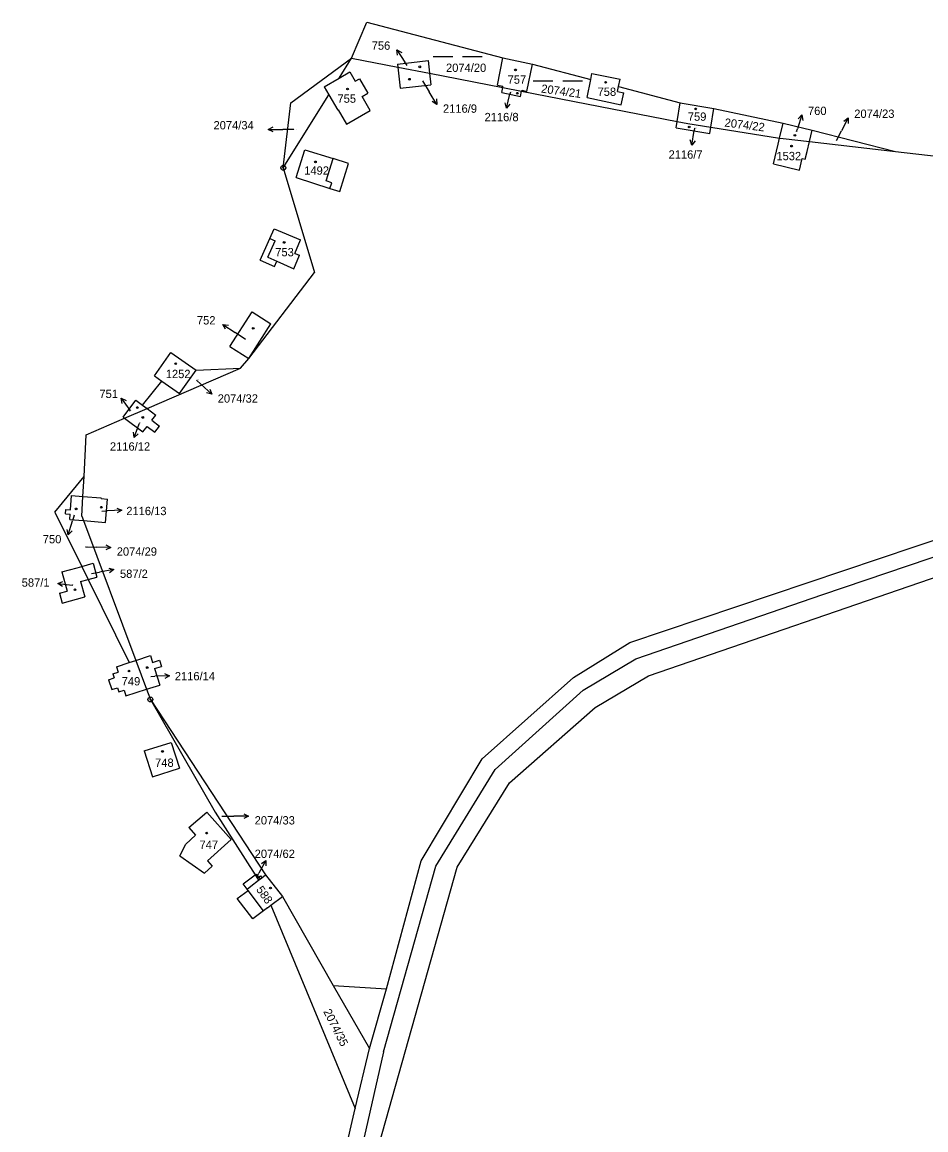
# Model space of a CAD drawing. Extents: x -763205 to -760228, y -1155311 to -1152844.
# Drawn here: x -762430.5 to -762245.9, y -1154041.9 to -1153815.6 of the extents above; entities that cross this region are included whole.
import ezdxf

# ---------------------------------------------------------------- set-up
doc = ezdxf.new("R2010")
doc.units = 0
for name, color, linetype in [('Vrstva 1', 7, 'Continuous'), ('Vrstva 10', 7, 'Continuous'), ('Vrstva 16', 7, 'Continuous'), ('Vrstva 18', 7, 'Continuous'), ('Vrstva 19', 7, 'Continuous'), ('Vrstva 24', 7, 'Continuous'), ('Vrstva 25', 7, 'Continuous'), ('Vrstva 4', 7, 'Continuous'), ('Vrstva 6', 7, 'Continuous')]:
    doc.layers.add(name, color=color, linetype=linetype)

msp = doc.modelspace()

# ---------------------------------------------------------------- linework, layer by layer
at = {"layer": 'Vrstva 1'}
for p, q in [((-762365.73, -1153827.07), (-762363.18, -1153822.97)), ((-762363.18, -1153822.97), (-762353.7, -1153824.82)), ((-762353.76, -1153824.23), (-762347.55, -1153823.47)), ((-762353.76, -1153824.23), (-762353.7, -1153824.82)), ((-762347.55, -1153823.47), (-762347.23, -1153826.07)), ((-762333.38, -1153828.49), (-762332.24, -1153822.94)), ((-762332.24, -1153822.94), (-762326.22, -1153824.18)), ((-762327.37, -1153829.76), (-762326.22, -1153824.18)), ((-762368.76, -1153828.84), (-762365.73, -1153827.07)), ((-762365.73, -1153827.07), (-762363.51, -1153825.78)), ((-762363.51, -1153825.78), (-762362.4, -1153827.69)), ((-762353.7, -1153824.82), (-762353.23, -1153829.12)), ((-762353.7, -1153824.82), (-762347.23, -1153826.07)), ((-762347.23, -1153826.07), (-762346.95, -1153828.41)), ((-762347.23, -1153826.07), (-762332.29, -1153828.98)), ((-762314.29, -1153827.31), (-762314.06, -1153826.1)), ((-762314.06, -1153826.1), (-762308.31, -1153827.26)), ((-762368.76, -1153828.84), (-762367.83, -1153830.44)), ((-762362.4, -1153827.69), (-762361.57, -1153827.21)), ((-762361.57, -1153827.21), (-762359.87, -1153830.12)), ((-762353.23, -1153829.12), (-762346.95, -1153828.41)), ((-762333.38, -1153828.49), (-762332.24, -1153828.73)), ((-762332.5, -1153829.96), (-762332.29, -1153828.98)), ((-762332.29, -1153828.98), (-762332.24, -1153828.73)), ((-762332.29, -1153828.98), (-762328.45, -1153829.73)), ((-762315.01, -1153831.04), (-762314.29, -1153827.31)), ((-762308.84, -1153829.79), (-762308.63, -1153828.8)), ((-762308.63, -1153828.8), (-762308.31, -1153827.26)), ((-762377.11, -1153845.38), (-762367.83, -1153830.44)), ((-762367.83, -1153830.44), (-762365.98, -1153833.61)), ((-762361.02, -1153830.78), (-762359.87, -1153830.12)), ((-762359.37, -1153833.66), (-762361.02, -1153830.78)), ((-762332.5, -1153829.96), (-762328.68, -1153830.79)), ((-762328.68, -1153830.79), (-762328.45, -1153829.73)), ((-762328.45, -1153829.73), (-762328.41, -1153829.54)), ((-762328.45, -1153829.73), (-762296.66, -1153835.92)), ((-762328.41, -1153829.54), (-762327.37, -1153829.76)), ((-762315.01, -1153831.04), (-762308.06, -1153832.5)), ((-762308.84, -1153829.79), (-762307.55, -1153830.06)), ((-762308.06, -1153832.5), (-762307.55, -1153830.06)), ((-762365.98, -1153833.61), (-762365.89, -1153833.56)), ((-762365.89, -1153833.56), (-762364.23, -1153836.46)), ((-762364.23, -1153836.46), (-762359.37, -1153833.66)), ((-762296.66, -1153835.92), (-762296.02, -1153832.12)), ((-762296.02, -1153832.12), (-762289.13, -1153833.27)), ((-762289.77, -1153837.08), (-762289.13, -1153833.27)), ((-762296.87, -1153837.2), (-762296.66, -1153835.92)), ((-762296.66, -1153835.92), (-762294.44, -1153836.35)), ((-762296.87, -1153837.2), (-762289.99, -1153838.4)), ((-762294.44, -1153836.35), (-762289.77, -1153837.08)), ((-762289.99, -1153838.4), (-762289.77, -1153837.08)), ((-762289.77, -1153837.08), (-762275.73, -1153839.29)), ((-762275.73, -1153839.29), (-762275.01, -1153836.29)), ((-762275.01, -1153836.29), (-762269.07, -1153837.69)), ((-762269.63, -1153840.02), (-762269.07, -1153837.69)), ((-762277, -1153844.56), (-762276.04, -1153840.57)), ((-762276.04, -1153840.57), (-762275.73, -1153839.29)), ((-762275.73, -1153839.29), (-762275, -1153839.4)), ((-762275, -1153839.4), (-762269.63, -1153840.02)), ((-762270.12, -1153842.08), (-762269.63, -1153840.02)), ((-762269.63, -1153840.02), (-762252.02, -1153842.05)), ((-762374.49, -1153847.39), (-762372.68, -1153841.68)), ((-762372.68, -1153841.68), (-762366.9, -1153843.51)), ((-762270.49, -1153843.63), (-762270.12, -1153842.08)), ((-762252.02, -1153842.05), (-762239.69, -1153843.48)), ((-762363.78, -1153844.5), (-762366.9, -1153843.51)), ((-762365.58, -1153850.24), (-762363.78, -1153844.5)), ((-762277, -1153844.56), (-762271.68, -1153845.85)), ((-762271.68, -1153845.85), (-762271.11, -1153843.48)), ((-762271.11, -1153843.48), (-762270.49, -1153843.63)), ((-762377.11, -1153845.38), (-762370.77, -1153866.79)), ((-762374.49, -1153847.39), (-762367.58, -1153849.6)), ((-762367.58, -1153849.6), (-762365.58, -1153850.24)), ((-762379.89, -1153859.84), (-762378.99, -1153857.82)), ((-762378.99, -1153857.82), (-762373.58, -1153860.13)), ((-762381.85, -1153864.23), (-762379.89, -1153859.84)), ((-762374.75, -1153862.86), (-762373.58, -1153860.13)), ((-762374.99, -1153866), (-762373.82, -1153863.26)), ((-762374.75, -1153862.86), (-762373.82, -1153863.26)), ((-762381.85, -1153864.23), (-762378.92, -1153865.57)), ((-762378.92, -1153865.57), (-762378.4, -1153864.44)), ((-762378.4, -1153864.44), (-762374.99, -1153866)), ((-762384.13, -1153884.34), (-762370.77, -1153866.79)), ((-762388.02, -1153881.92), (-762383.47, -1153874.82)), ((-762383.47, -1153874.82), (-762379.65, -1153877.23)), ((-762384.13, -1153884.34), (-762379.65, -1153877.23)), ((-762403.45, -1153887.86), (-762400.08, -1153883.1)), ((-762400.08, -1153883.1), (-762394.94, -1153886.74)), ((-762388.02, -1153881.92), (-762384.13, -1153884.34)), ((-762385.85, -1153886.35), (-762384.13, -1153884.34)), ((-762404.95, -1153894.58), (-762385.85, -1153886.35)), ((-762403.45, -1153887.86), (-762401.9, -1153888.96)), ((-762398.31, -1153891.5), (-762394.94, -1153886.74)), ((-762401.9, -1153888.96), (-762398.31, -1153891.5)), ((-762409.79, -1153896.35), (-762407.22, -1153892.87)), ((-762409.52, -1153896.55), (-762404.95, -1153894.58)), ((-762407.22, -1153892.87), (-762405.88, -1153893.88)), ((-762405.88, -1153893.88), (-762404.95, -1153894.58)), ((-762404.95, -1153894.58), (-762403.18, -1153895.91)), ((-762417.36, -1153899.93), (-762409.52, -1153896.55)), ((-762409.79, -1153896.35), (-762409.52, -1153896.55)), ((-762409.52, -1153896.55), (-762405.8, -1153899.36)), ((-762403.99, -1153896.97), (-762403.18, -1153895.91)), ((-762403.99, -1153896.97), (-762402.43, -1153898.15)), ((-762405.8, -1153899.36), (-762404.93, -1153898.21)), ((-762404.93, -1153898.21), (-762403.37, -1153899.39)), ((-762403.37, -1153899.39), (-762402.43, -1153898.15)), ((-762417.81, -1153908.43), (-762417.36, -1153899.93)), ((-762418.03, -1153912.51), (-762417.81, -1153908.43)), ((-762306.29, -1153942.34), (-762207.83, -1153909.23)), ((-762420.58, -1153915.27), (-762420.36, -1153912.33)), ((-762420.36, -1153912.33), (-762418.03, -1153912.51)), ((-762418.24, -1153916.56), (-762418.03, -1153912.51)), ((-762418.03, -1153912.51), (-762414.29, -1153912.81)), ((-762414.31, -1153912.96), (-762414.29, -1153912.81)), ((-762414.31, -1153912.96), (-762413.01, -1153913.06)), ((-762413.41, -1153917.83), (-762413.01, -1153913.06)), ((-762421.62, -1153916.1), (-762421.55, -1153915.2)), ((-762421.55, -1153915.2), (-762420.58, -1153915.27)), ((-762421.62, -1153916.1), (-762420.64, -1153916.17)), ((-762420.72, -1153917.22), (-762420.64, -1153916.17)), ((-762420.72, -1153917.22), (-762417.91, -1153917.45)), ((-762418.24, -1153916.56), (-762417.91, -1153917.45)), ((-762417.91, -1153917.45), (-762413.41, -1153917.83)), ((-762417.91, -1153917.45), (-762407.24, -1153946.03)), ((-762302.52, -1153949.17), (-762204.97, -1153915.64)), ((-762418.28, -1153926.85), (-762415.96, -1153926.18)), ((-762415.96, -1153926.18), (-762415.19, -1153929.03)), ((-762422.32, -1153927.9), (-762419.2, -1153927.12)), ((-762422.32, -1153927.9), (-762421.23, -1153931.86)), ((-762419.2, -1153927.12), (-762418.28, -1153926.85)), ((-762418.51, -1153929.94), (-762416.96, -1153929.52)), ((-762418.51, -1153929.94), (-762417.65, -1153933.06)), ((-762416.96, -1153929.52), (-762415.19, -1153929.03)), ((-762422.8, -1153932.29), (-762421.23, -1153931.86)), ((-762422.8, -1153932.29), (-762422.27, -1153934.35)), ((-762422.27, -1153934.35), (-762417.65, -1153933.06)), ((-762317.85, -1153949.52), (-762306.29, -1153942.34)), ((-762411.2, -1153947.32), (-762408.6, -1153946.47)), ((-762408.6, -1153946.47), (-762407.24, -1153946.03)), ((-762407.24, -1153946.03), (-762404.26, -1153945.06)), ((-762407.24, -1153946.03), (-762405.04, -1153951.93)), ((-762404.26, -1153945.06), (-762403.81, -1153946.46)), ((-762403.81, -1153946.46), (-762402.37, -1153945.99)), ((-762402.37, -1153945.99), (-762401.96, -1153947.24)), ((-762411.93, -1153948.76), (-762410.84, -1153948.41)), ((-762411.93, -1153948.76), (-762411.65, -1153949.61)), ((-762411.2, -1153947.32), (-762410.84, -1153948.41)), ((-762403.4, -1153947.71), (-762401.96, -1153947.24)), ((-762403.4, -1153947.71), (-762402.32, -1153951.08)), ((-762313.42, -1153955.63), (-762302.52, -1153949.17)), ((-762412.79, -1153949.98), (-762411.65, -1153949.61)), ((-762412.79, -1153949.98), (-762412.14, -1153951.97)), ((-762405.04, -1153951.93), (-762402.32, -1153951.08)), ((-762336.52, -1153966.17), (-762317.85, -1153949.52)), ((-762412.14, -1153951.97), (-762411.01, -1153951.6)), ((-762411.01, -1153951.6), (-762410.73, -1153952.46)), ((-762410.73, -1153952.46), (-762409.64, -1153952.1)), ((-762409.64, -1153952.1), (-762409.27, -1153953.24)), ((-762409.27, -1153953.24), (-762405.04, -1153951.93)), ((-762405.04, -1153951.93), (-762404.26, -1153954.02)), ((-762404.26, -1153954.02), (-762380.73, -1153989.83)), ((-762330.92, -1153971.05), (-762313.42, -1153955.63)), ((-762405.54, -1153964.53), (-762400.01, -1153962.78)), ((-762400.01, -1153962.78), (-762398.32, -1153968.04)), ((-762405.54, -1153964.53), (-762403.85, -1153969.81)), ((-762348.93, -1153987.01), (-762336.52, -1153966.17)), ((-762403.85, -1153969.81), (-762398.32, -1153968.04)), ((-762341.62, -1153988.29), (-762330.92, -1153971.05)), ((-762396.42, -1153980.19), (-762392.71, -1153977.03)), ((-762392.71, -1153977.03), (-762387.73, -1153982.61)), ((-762396.42, -1153980.19), (-762395.05, -1153981.76)), ((-762397.02, -1153983.55), (-762395.05, -1153981.76)), ((-762392.61, -1153986.99), (-762387.73, -1153982.61)), ((-762398.22, -1153985.97), (-762397.02, -1153983.55)), ((-762398.22, -1153985.97), (-762393.21, -1153989.53)), ((-762392.61, -1153986.99), (-762391.61, -1153988.1)), ((-762356.01, -1154013.13), (-762348.93, -1153987.01)), ((-762393.21, -1153989.53), (-762391.61, -1153988.1)), ((-762385.31, -1153991.71), (-762382.85, -1153989.87)), ((-762382.85, -1153989.87), (-762382.63, -1153989.71)), ((-762382.63, -1153989.71), (-762382.15, -1153990.35)), ((-762381.51, -1153990.44), (-762380.73, -1153989.83)), ((-762380.73, -1153989.83), (-762377.29, -1153994.25)), ((-762363.03, -1154064.25), (-762341.62, -1153988.29)), ((-762384.49, -1153992.78), (-762385.31, -1153991.71)), ((-762382.16, -1153990.95), (-762381.51, -1153990.44)), ((-762382.15, -1153990.35), (-762381.78, -1153990.07)), ((-762381.78, -1153990.07), (-762381.51, -1153990.44)), ((-762386.51, -1153994.66), (-762384.32, -1153993.01)), ((-762384.32, -1153993.01), (-762384.49, -1153992.78)), ((-762379.64, -1153996.04), (-762377.29, -1153994.25)), ((-762377.29, -1153994.25), (-762366.9, -1154012.43)), ((-762383.32, -1153998.84), (-762386.51, -1153994.66)), ((-762380.35, -1153996.58), (-762381.16, -1153997.2)), ((-762380.35, -1153996.58), (-762379.64, -1153996.04)), ((-762381.16, -1153997.2), (-762383.32, -1153998.84)), ((-762366.9, -1154012.43), (-762356.01, -1154013.13)), ((-762359.53, -1154025.33), (-762356.01, -1154013.13)), ((-762362.41, -1154037.61), (-762359.53, -1154025.33)), ((-762366.48, -1154054.98), (-762362.41, -1154037.61))]:
    msp.add_line(p, q, dxfattribs=at)
at = {"layer": 'Vrstva 10'}
for p, q in [((-762266.9, -1153932.54), (-762236.2, -1153922.19)), ((-762305.1, -1153945.73), (-762266.9, -1153932.54)), ((-762315.83, -1153952.13), (-762305.1, -1153945.73)), ((-762333.86, -1153968.33), (-762315.83, -1153952.13)), ((-762345.92, -1153988.07), (-762333.86, -1153968.33)), ((-762356.66, -1154026.02), (-762345.92, -1153988.07)), ((-762356.66, -1154026.02), (-762361.72, -1154048.42))]:
    msp.add_line(p, q, dxfattribs=at)
at = {"layer": 'Vrstva 16'}
for p, q in [((-762353.886, -1153821.263), (-762352.27, -1153823.79)), ((-762351.83, -1153824.48), (-762352.27, -1153823.79)), ((-762348.7, -1153827.59), (-762347.3, -1153829.87)), ((-762345.731, -1153832.427), (-762347.3, -1153829.87)), ((-762331.53, -1153833.227), (-762330.83, -1153830.31)), ((-762330.73, -1153829.9), (-762330.83, -1153830.31)), ((-762271.173, -1153834.587), (-762272.1, -1153837.44)), ((-762261.723, -1153835.18), (-762263.09, -1153837.85)), ((-762380.21, -1153837.531), (-762377.21, -1153837.53)), ((-762374.93, -1153837.53), (-762377.21, -1153837.53)), ((-762293.626, -1153840.755), (-762293.17, -1153837.79)), ((-762293.1, -1153837.31), (-762293.17, -1153837.79)), ((-762272.27, -1153837.97), (-762272.1, -1153837.44)), ((-762264.08, -1153839.79), (-762263.09, -1153837.85)), ((-762389.446, -1153877.386), (-762386.95, -1153879.05)), ((-762384.86, -1153880.45), (-762386.95, -1153879.05)), ((-762394.85, -1153888.77), (-762393.94, -1153889.62)), ((-762391.742, -1153891.661), (-762393.94, -1153889.62)), ((-762410.213, -1153892.421), (-762408.48, -1153894.87)), ((-762408.29, -1153895.13), (-762408.48, -1153894.87)), ((-762407.576, -1153900.483), (-762406.56, -1153897.66)), ((-762406.51, -1153897.51), (-762406.56, -1153897.66)), ((-762421.034, -1153920.396), (-762420.18, -1153917.52)), ((-762419.82, -1153916.32), (-762420.18, -1153917.52)), ((-762414.16, -1153915.55), (-762413.06, -1153915.5)), ((-762410.063, -1153915.36), (-762413.06, -1153915.5)), ((-762417.52, -1153922.82), (-762415.37, -1153922.87)), ((-762412.371, -1153922.934), (-762415.37, -1153922.87)), ((-762416.31, -1153928.29), (-762414.66, -1153928)), ((-762411.707, -1153927.473), (-762414.66, -1153928)), ((-762423.164, -1153930.332), (-762420.18, -1153930.64)), ((-762420.07, -1153930.65), (-762420.18, -1153930.64)), ((-762404.16, -1153949.31), (-762403.35, -1153949.28)), ((-762400.352, -1153949.161), (-762403.35, -1153949.28)), ((-762389.67, -1153977.85), (-762387.2, -1153977.85)), ((-762384.2, -1153977.851), (-762387.2, -1153977.85)), ((-762380.662, -1153986.892), (-762382.09, -1153989.53)), ((-762382.46, -1153990.2), (-762382.09, -1153989.53))]:
    msp.add_line(p, q, dxfattribs=at)
for points in [[(-762353.769, -1153822.375), (-762353.886, -1153821.263), (-762352.926, -1153821.836)], [(-762345.828, -1153831.313), (-762345.731, -1153832.427), (-762346.68, -1153831.836)], [(-762330.811, -1153832.371), (-762331.53, -1153833.227), (-762331.783, -1153832.138)], [(-762271.957, -1153835.383), (-762271.173, -1153834.587), (-762271.006, -1153835.692)], [(-762262.624, -1153835.842), (-762261.723, -1153835.18), (-762261.733, -1153836.298)], [(-762379.21, -1153838.03), (-762380.21, -1153837.531), (-762379.21, -1153837.03)], [(-762292.98, -1153839.843), (-762293.626, -1153840.755), (-762293.968, -1153839.691)], [(-762388.892, -1153878.357), (-762389.446, -1153877.386), (-762388.337, -1153877.525)], [(-762410.044, -1153893.526), (-762410.213, -1153892.421), (-762409.227, -1153892.949)], [(-762392.134, -1153890.615), (-762391.742, -1153891.661), (-762392.815, -1153891.347)], [(-762406.767, -1153899.711), (-762407.576, -1153900.483), (-762407.708, -1153899.372)], [(-762411.085, -1153914.907), (-762410.063, -1153915.36), (-762411.039, -1153915.906)], [(-762420.27, -1153919.58), (-762421.034, -1153920.396), (-762421.229, -1153919.295)], [(-762413.36, -1153922.413), (-762412.371, -1153922.934), (-762413.381, -1153923.413)], [(-762412.779, -1153927.156), (-762411.707, -1153927.473), (-762412.603, -1153928.141)], [(-762422.221, -1153930.932), (-762423.164, -1153930.332), (-762422.118, -1153929.937)], [(-762401.371, -1153948.701), (-762400.352, -1153949.161), (-762401.332, -1153949.7)], [(-762385.2, -1153977.351), (-762384.2, -1153977.851), (-762385.2, -1153978.351)], [(-762381.578, -1153987.533), (-762380.662, -1153986.892), (-762380.698, -1153988.009)]]:
    msp.add_lwpolyline(points, dxfattribs=at)
at = {"layer": 'Vrstva 24'}
for centre, radius in [((-762377.11, -1153845.38), 0.5), ((-762377.11, -1153845.38), 0.1), ((-762404.26, -1153954.02), 0.5), ((-762404.26, -1153954.02), 0.1)]:
    msp.add_circle(centre, radius, dxfattribs=at)
at = {"layer": 'Vrstva 25'}
for p, q in [((-762346.515, -1153822.64), (-762342.495, -1153822.64)), ((-762340.485, -1153822.64), (-762336.465, -1153822.64)), ((-762326.045, -1153827.63), (-762322.025, -1153827.63)), ((-762320.015, -1153827.63), (-762315.995, -1153827.63))]:
    msp.add_line(p, q, dxfattribs=at)
for centre in [(-762349.23, -1153824.75), (-762329.68, -1153825.38), (-762363.98, -1153829.29), (-762351.35, -1153827.28), (-762311.26, -1153827.91), (-762329.31, -1153830.15), (-762292.87, -1153833.35), (-762294.19, -1153837.04), (-762272.61, -1153838.74), (-762273.28, -1153840.95), (-762370.54, -1153844.18), (-762376.93, -1153860.63), (-762383.26, -1153878.18), (-762399.09, -1153885.41), (-762406.93, -1153894.37), (-762405.81, -1153896.39), (-762419.44, -1153915.07), (-762414.29, -1153914.73), (-762419.66, -1153931.6), (-762408.64, -1153948.2), (-762404.9, -1153947.49), (-762401.79, -1153964.62), (-762392.76, -1153981.32), (-762382.11, -1153990.59), (-762379.72, -1153992.54)]:
    msp.add_circle(centre, 0.175, dxfattribs=at)
at = {"layer": 'Vrstva 4'}
for p, q in [((-762368.36, -1153848.06), (-762366.9, -1153843.51)), ((-762367.21, -1153848.43), (-762368.36, -1153848.06)), ((-762367.58, -1153849.6), (-762367.21, -1153848.43)), ((-762380.29, -1153863.67), (-762378.8, -1153860.33)), ((-762379.89, -1153859.84), (-762378.8, -1153860.33)), ((-762380.29, -1153863.67), (-762378.4, -1153864.44)), ((-762384.49, -1153992.78), (-762383.71, -1153992.16)), ((-762383.71, -1153992.16), (-762382.16, -1153990.95)), ((-762381.16, -1153997.2), (-762384.32, -1153993.01)), ((-762366.9, -1154012.43), (-762359.53, -1154025.33))]:
    msp.add_line(p, q, dxfattribs=at)
at = {"layer": 'Vrstva 6'}
for p, q in [((-762363.18, -1153822.97), (-762360.04, -1153815.62)), ((-762360.04, -1153815.62), (-762332.24, -1153822.94)), ((-762375.58, -1153832.13), (-762363.18, -1153822.97)), ((-762326.22, -1153824.18), (-762314.29, -1153827.31)), ((-762308.63, -1153828.8), (-762296.02, -1153832.12)), ((-762377.11, -1153845.38), (-762375.58, -1153832.13)), ((-762289.13, -1153833.27), (-762275.01, -1153836.29)), ((-762269.07, -1153837.69), (-762252.02, -1153842.05)), ((-762394.94, -1153886.74), (-762385.85, -1153886.35)), ((-762405.88, -1153893.88), (-762401.9, -1153888.96)), ((-762423.78, -1153915.71), (-762417.81, -1153908.43)), ((-762423.78, -1153915.71), (-762418.28, -1153926.85)), ((-762418.28, -1153926.85), (-762416.96, -1153929.52)), ((-762416.96, -1153929.52), (-762408.6, -1153946.47)), ((-762404.26, -1153954.02), (-762391.04, -1153977.05)), ((-762391.04, -1153977.05), (-762382.85, -1153989.87)), ((-762382.85, -1153989.87), (-762382.16, -1153990.95)), ((-762379.64, -1153996.04), (-762362.41, -1154037.61))]:
    msp.add_line(p, q, dxfattribs=at)

# ---------------------------------------------------------------- texts
at = {"layer": 'Vrstva 16'}
for s, p in [('756', (-762359.05, -1153821.26)), ('2116/9', (-762344.493, -1153834.13)), ('760', (-762269.933, -1153834.59)), ('2074/23', (-762260.483, -1153835.18)), ('2074/34', (-762391.366, -1153837.53)), ('2116/8', (-762335.998, -1153835.86)), ('2116/7', (-762298.408, -1153843.51)), ('752', (-762394.757, -1153877.39)), ('751', (-762414.674, -1153892.42)), ('2074/32', (-762390.503, -1153893.36)), ('2116/12', (-762412.528, -1153903.17)), ('2116/13', (-762409.183, -1153916.35)), ('750', (-762426.243, -1153922.1)), ('2074/29', (-762411.133, -1153924.63)), ('587/2', (-762410.473, -1153929.17)), ('587/1', (-762430.545, -1153930.97)), ('2116/14', (-762399.273, -1153950.1)), ('2074/33', (-762382.963, -1153979.55)), ('2074/62', (-762382.956, -1153986.39))]:
    msp.add_text(s, height=1.7, dxfattribs=at).set_placement(p)
at = {"layer": 'Vrstva 18'}
for s, height, p in [('2074/20', 1.7, (-762343.873, -1153825.79)), ('2116/9', 0.1, (-762348.686, -1153827.59)), ('2116/8', 0.1, (-762330.716, -1153829.9)), ('2074/34', 0.1, (-762374.916, -1153837.53)), ('2116/7', 0.1, (-762293.086, -1153837.31)), ('2074/23', 0.1, (-762264.066, -1153839.79)), ('2074/32', 0.1, (-762394.836, -1153888.77)), ('2116/12', 0.1, (-762406.496, -1153897.51)), ('2116/13', 0.1, (-762414.146, -1153915.55)), ('2074/29', 0.1, (-762417.506, -1153922.82)), ('2116/14', 0.1, (-762404.146, -1153949.31)), ('2074/33', 0.1, (-762389.656, -1153977.85)), ('2074/62', 0.1, (-762382.751, -1153990.2))]:
    msp.add_text(s, height=height, dxfattribs=at).set_placement(p)
for s, rotation, p in [('2074/21', 352.13986, (-762324.515, -1153829.992)), ('2074/22', 352.77011, (-762287.044, -1153836.93)), ('2074/35', 296.84943, (-762368.983, -1154017.752))]:
    msp.add_text(s, height=1.7, rotation=rotation, dxfattribs=at).set_placement(p)
at = {"layer": 'Vrstva 19'}
for s, height, p in [('756', 0.1, (-762351.816, -1153824.48)), ('757', 1.7, (-762331.293, -1153828.21)), ('758', 1.7, (-762312.913, -1153830.69)), ('755', 1.7, (-762366.048, -1153832.09)), ('759', 1.7, (-762294.473, -1153835.77)), ('760', 0.1, (-762272.256, -1153837.97)), ('1532', 1.7, (-762276.383, -1153843.83)), ('1492', 1.7, (-762372.839, -1153846.79)), ('753', 1.7, (-762378.753, -1153863.46)), ('752', 0.1, (-762384.846, -1153880.45)), ('1252', 1.7, (-762401.117, -1153888.35)), ('751', 0.1, (-762408.276, -1153895.13)), ('750', 0.1, (-762419.806, -1153916.32)), ('587/2', 0.1, (-762416.296, -1153928.29)), ('587/1', 0.1, (-762420.056, -1153930.65)), ('749', 1.7, (-762410.123, -1153951.14)), ('748', 1.7, (-762403.303, -1153967.78)), ('747', 1.7, (-762394.223, -1153984.54))]:
    msp.add_text(s, height=height, dxfattribs=at).set_placement(p)
msp.add_text('588', height=1.7, rotation=305.55839, dxfattribs=at).set_placement((-762382.742, -1153992.873))

doc.saveas('drawing.dxf')
